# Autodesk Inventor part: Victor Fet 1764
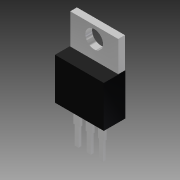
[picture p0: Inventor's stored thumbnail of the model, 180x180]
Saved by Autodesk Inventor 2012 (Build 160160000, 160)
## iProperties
Shininess: 64.0
Length Units: 11272
Angle Units: 11279
Time Units: 11290
Mass Units: 11286
Length Display Precision: 3
Angle Display Precision: 2
Compacted: True
Part Number: Victor Fet 1764
Document SubType Name: Modeling
Created: 2007-01
Designer: uidk0133
Density: 1 g/cm^3
Material: Default
Density: 0.0
Volumn: 0.0
Area: 0.0
PropertySet Name: Model Information
Control State: 0
Master: False
Checked Out: False
Author: uidk0133
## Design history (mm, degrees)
sketch "Sketch1"
  geometry: L1 (-5.08, 8.636)-(5.08, 8.636); L2 (5.08, 8.636)-(5.08, 0); L3 (5.08, 0)-(-5.08, 0); L4 (-5.08, 0)-(-5.08, 8.636); 2 further points
  constraints: 8 end point, 2 parallel, 1 coincident, 1 horizontal, 1 midpoint, 1 perpendicular, 1 other
  dimensions: "d0" = 10.16 distance of L1.start L1.end; "d1" = 8.636 distance of L1.end L2.end
extrude "Extrusion1" new body sketch "Sketch1" distance "d2" = 4.4704; taper "d3" = 0 deg
sketch "Sketch2"
  geometry: L1 (0.089, -1.397)-(10.071, -1.397); L2 (10.071, -1.397)-(10.071, 0); L3 (10.071, 0)-(0.089, 0); L4 (0.089, 0)-(0.089, -1.397); L5 (0, 0)-(10.16, 0) reference; 1 further point
  constraints: 8 end point, 2 midpoint, 2 parallel, 1 horizontal, 1 perpendicular
  dimensions: "d7" = 1.397 distance of L3.end L1.start; "d8" = 9.9822 distance of L1.start L1.end
extrude "Extrusion2" join sketch "Sketch2" distance "d5" = 6.35; taper "d6" = 0 deg
sketch "Sketch3"
  geometry: L1 (9.982, 6.35)-(0, 6.35) reference; L2 (9.982, 0)-(9.982, 6.35) reference; L3 (4.991, 6.35)-(4.991, 1.588); 1 further point
  constraints: 2 end point, 1 midpoint, 1 parallel, 1 point on line
  dimensions: "d9" = 2.54 distance from line of L1 point (4.991, 3.81)
hole "Hole1" sketch "Sketch3" at (4.991, 3.81) diameter "d10" = 3.683; stored, may be unused: countersink angle "d14" = 82 deg, drill point angle "d16" = 118 deg; dims "d11" = 12.7, "d12" = 9.525, "d13" = 6.35, "d15" = 19.05
sketch "Sketch4"
  geometry: L1 (0, 0)-(0, 4.47) reference; L2 (10.16, 0)-(10.16, 4.47) reference; L3 (0, 2.235)-(10.16, 2.235); L4 (1.905, 2.527)-(3.175, 2.527); L5 (3.175, 2.527)-(3.175, 1.943); L6 (3.175, 1.943)-(1.905, 1.943); L7 (1.905, 1.943)-(1.905, 2.527); 1 further point
  constraints: 10 end point, 3 midpoint, 2 parallel, 1 horizontal, 1 perpendicular, 1 point on line
  dimensions: "d17" = 0.5842 distance of L4.end L5.end; "d18" = 1.27 distance of L5.end L6.end; "d19" = 1.905 distance from line of L1 L4.start
extrude "Extrusion3" join sketch "Sketch4" distance "d20" = 3.81; taper "d21" = 0 deg
sketch "Sketch5"
  geometry: L1 (1.905, 2.527)-(3.175, 2.527) reference; L2 (3.175, 1.943)-(1.905, 1.943) reference; L3 (2.134, 2.527)-(2.946, 2.527); L4 (2.946, 2.527)-(2.946, 1.943); L5 (2.946, 1.943)-(2.134, 1.943); L6 (2.134, 1.943)-(2.134, 2.527); 1 further point
  constraints: 8 end point, 2 midpoint, 2 parallel, 2 point on line, 1 horizontal, 1 perpendicular
  dimensions: "d22" = 0.8128 distance between parallel lines of L4 L6
extrude "Extrusion4" join sketch "Sketch5" distance "d23" = 3.81; taper "d24" = 0 deg
pattern_linear "Rectangular Pattern1" dims "d27" = 2.54
body "Solid1"
